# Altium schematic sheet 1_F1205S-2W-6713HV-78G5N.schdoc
size 289 x 200 mm; Name: default297x210; Symbol: default297x210; Device: default297x210; Date: 2025.06.19; Rev: V1.1; Size: "A4"; Id: /; File: F1205S-2W-6713HV-78G5N; Sheet: /; @Page No: 1; @Page Count: 1; @Schematic Name: F1205S-2W-6713HV-78G5N; @Project Name: F1205S-2W-6713HV-78G5N; @Board Name: F1205S-2W-6713HV-78G5N; @Update Date: 2025-06-12; @Create Time: 14:34:34; @Update Time: 14:34:42; @Page Name: F1205S-2W-6713HV-78G5N; @Create Date: 2025-06-12
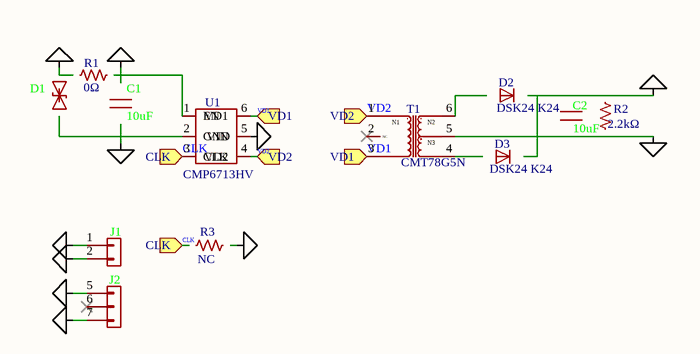
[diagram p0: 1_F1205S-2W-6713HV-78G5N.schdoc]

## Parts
C1  10uF  [C0603]
C2  10uF  [C0603]
D1  (no value)  [SOD-123FL_L2.8-W1.8-LS3.7-BI]
D2  DSK24 K24  [SOD-123_L2.8-W1.8-LS3.7-RD]
D3  DSK24 K24  [SOD-123_L2.8-W1.8-LS3.7-RD]
J1  Connector_Generic_Conn_01x04  [coileasy:PinHeader_01x02_P2.54mm_Vertical]  (value not drawn)
J2  Connector_Generic_Conn_01x04  [coileasy:PinHeader_01x03_1_P2.54mm_Vertical]  (value not drawn)
R1  0Ω  [R0603]
R2  2.2kΩ  [R0603]
R3  NC  [R0603]
T1  CMT78G5N  [SMD-6_L9.7-W8.9-P2.54-LS12.8-TL]
U1  value CMP6713HV  [coileasy:SOT-23-6]  (hidden comment: Coileasy_SOT23-6)

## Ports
CLK (in), VD1 (in), VD2 (in)

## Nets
0V: J2.5 T1.5
+VO: J2.7
GND: J1.2 U1.2(GND)
VCC: U1.1(EN) U1.5(VIN)
VIN: J1.1
CLK: U1.3(CLK) ; port CLK
VD1: T1.3 U1.6(VD1) ; port VD1
VD2: T1.1 U1.4(VD2) ; port VD2

Not connected (* = marked no-connect by the designer): J2 6*; T1 2* 4 6

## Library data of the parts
C1 C2 = 0603X106M250NT: Manufacturer: FH(风华); Symbol: My_Library_C; Add into BOM: yes; Tolerance: ±20%; Voltage Rating: 25V; Temperature Coefficient: X5R
D1 = SMF28CA_C364280: Symbol: Device_D_TVS; Add into BOM: yes; polarity: 双向; Type: TVS
D2 D3 = DSK24 K24: Manufacturer: MDD(辰达半导体); Symbol: My_Library_D; Add into BOM: yes; Diode Configuration: 独立式; Forward Voltage (Vf@If): 550mV@2A; Reverse Voltage (Vr): 40V; Rectified Current: 2A; Reverse Leakage Current (Ir): 500uA@40V
J1 = Connector_Generic_Conn_01x04: Symbol: Conn_01x04_1; ki_fp_filters: Connector*:*_1x??_*; Value: Conn_01x02; Add into BOM: yes
J2 = Connector_Generic_Conn_01x04: ki_fp_filters: Connector*:*_1x??_*; Value: Conn_01x03; Add into BOM: yes
R1 = RC0603FR-070RL: Manufacturer: YAGEO(国巨); Symbol: My_Library_R; Add into BOM: yes; Tolerance: ±1%; Power(Watts): 100mW; Voltage-Supply(Max): 75V
R2 = RC0603FR-072K2L: Manufacturer: YAGEO(国巨); Symbol: My_Library_R; Add into BOM: yes; Tolerance: ±1%; Power(Watts): 100mW; Voltage-Supply(Max): 75V; Temperature Coefficient: ±100ppm/℃
R3 = RC0603FR-0715KL: Symbol: My_Library_R; Add into BOM: yes; Tolerance: ±1%; Power(Watts): 100mW; Overload Voltage (Max): 75V; Temperature Coefficient: ±100ppm/℃
T1 = CMT78G5N: Manufacturer: coileasy(线易); Symbol: MYLibrary _CMT6870N; Add into BOM: yes
U1 = Coileasy_SOT23-6: Add into BOM: yes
